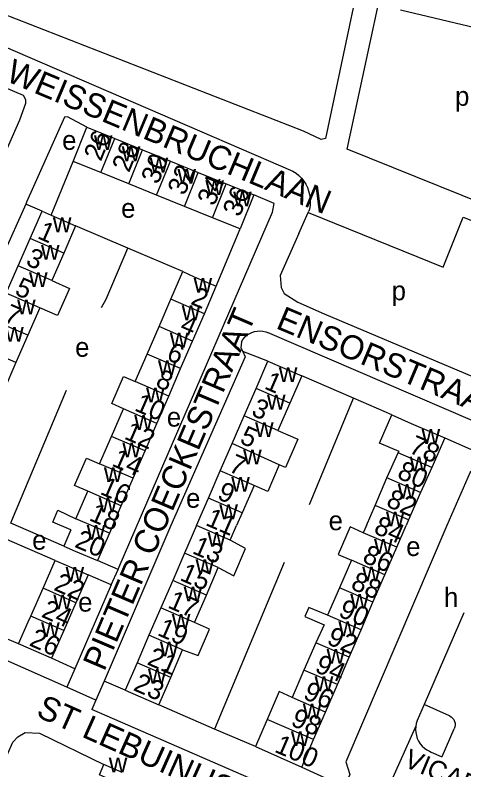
# Model space of a CAD drawing. Extents: x 162804 to 165059, y 381530 to 382901.
# Drawn here: x 163352.5 to 163445.8, y 381949.2 to 382106.1 of the extents above; entities that cross this region are included whole.
import ezdxf

# ---------------------------------------------------------------- set-up
doc = ezdxf.new("R2010")
doc.units = 0
for name, color, linetype in [('BLT_Basislijn', 7, 'Continuous'), ('BLT_Bebouwing', 7, 'Continuous'), ('BLT_Centroide', 7, 'Continuous'), ('BLT_Huisnummer', 7, 'Continuous'), ('BLT_Huisnummer_ tussenligend', 7, 'Continuous'), ('BLT_Onderverdeling_panden', 7, 'Continuous'), ('BLT_Straatnaam', 7, 'Continuous'), ('BLT_Straatnaam_verkleind', 7, 'Continuous'), ('BLT_Vlakafsluiter', 7, 'Continuous')]:
    doc.layers.add(name, color=color, linetype=linetype)

msp = doc.modelspace()

# ---------------------------------------------------------------- linework, layer by layer
at = {"layer": 'BLT_Basislijn'}
for p, q in [((163432.58, 382107.21), (163472.75, 382097.61)), ((163350, 382099.73), (163410.26, 382073.66)), ((163359.99, 382064.53), (163364.56, 382075.71)), ((163354.73, 382066.84), (163350, 382056.14)), ((163358.12, 382065.34), (163354.73, 382066.84)), ((163411.46, 382060.73), (163413.44, 382065.06)), ((163413.44, 382065.06), (163413.57, 382065.34)), ((163375.96, 382057.66), (163365.08, 382062.3)), ((163394.32, 382049.74), (163399.3, 382061.66)), ((163387.36, 382052.79), (163375.96, 382057.66)), ((163447.67, 382021.74), (163404.98, 382040.15)), ((163405.06, 382034.18), (163399.81, 382036.15)), ((163422.85, 382026.47), (163412.07, 382031.14)), ((163413.67, 382004.4), (163422.85, 382026.47)), ((163430.8, 382023.05), (163422.85, 382026.47)), ((163441.79, 382018.23), (163450.32, 382014.5)), ((163362.64, 381995.71), (163351.65, 382000.48)), ((163384.9, 382000), (163371.02, 381967.68)), ((163442.21, 382000), (163421.25, 381950.88)), ((163360.86, 381992.74), (163350.32, 381997.3)), ((163373.9, 381990.88), (163369.63, 381992.72)), ((163408.41, 381992.34), (163393.95, 381957.7)), ((163372.51, 381987.67), (163373.9, 381990.88)), ((163372.51, 381987.67), (163367.69, 381989.74)), ((163372.51, 381987.67), (163364.95, 381970.23)), ((163445.79, 381981.86), (163437.52, 381962.79)), ((163353.24, 381975.42), (163350, 381976.82)), ((163363.28, 381966.38), (163350, 381972.31)), ((163364.95, 381970.23), (163360.07, 381972.42)), ((163364.95, 381970.23), (163363.28, 381966.38)), ((163371.02, 381967.68), (163369.31, 381963.68)), ((163375.38, 381965.8), (163371.02, 381967.68)), ((163369.31, 381963.68), (163363.28, 381966.38)), ((163369.31, 381963.68), (163368.49, 381961.77)), ((163393.95, 381957.7), (163382.39, 381962.76)), ((163437.52, 381962.79), (163436.08, 381959.47)), ((163442.79, 381960.44), (163437.52, 381962.79)), ((163414.35, 381941.82), (163368.49, 381961.77)), ((163402.45, 381954.04), (163393.95, 381957.7)), ((163412.08, 381949.8), (163420.93, 381945.73))]:
    msp.add_line(p, q, dxfattribs=at)
for points in [[(163350, 382150.26), (163427.51, 382132.02), (163427.76, 382131.26), (163417.05, 382080.47), (163416.15, 382080.25), (163412.43, 382081.95), (163350, 382106.4)], [(163461.51, 382062.99), (163459.69, 382062.86), (163421.54, 382078.27), (163432.84, 382130.7), (163443.64, 382128.25), (163444.42, 382128.06), (163445.13, 382121.86)], [(163350, 382076.32), (163353.5, 382084.32), (163354.76, 382087.77), (163354.75, 382088.47), (163354.27, 382089.42), (163350.18, 382091.16)], [(163367.43, 382082.79), (163363.4, 382084.96), (163362.77, 382084.88), (163354.9, 382067.22), (163354.73, 382066.84)], [(163410.26, 382073.66), (163410.9, 382073.24), (163411.49, 382072.75), (163412.02, 382072.21), (163412.5, 382071.61), (163412.91, 382070.97), (163413.25, 382070.28), (163413.52, 382069.57), (163413.71, 382068.83), (163413.82, 382068.08), (163413.86, 382067.31), (163413.81, 382066.55), (163413.69, 382065.8), (163413.57, 382065.34)], [(163373.9, 381990.88), (163374.12, 381991.39), (163406, 382065.12), (163406.38, 382066.93), (163402.16, 382068.73)], [(163413.44, 382065.06), (163441.5, 382053.69), (163445.66, 382064.13), (163459.84, 382058.5)], [(163411.46, 382060.73), (163407.59, 382051.95), (163407.84, 382049.46), (163408.46, 382048.23), (163411.27, 382046.47), (163416.75, 382043.99), (163449.25, 382030.27)], [(163370.45, 382045.31), (163371.47, 382047.06), (163375.96, 382057.66)], [(163399.55, 382038.22), (163399.87, 382038.71), (163400.25, 382039.16), (163400.69, 382039.55), (163401.18, 382039.88), (163401.71, 382040.14), (163402.27, 382040.33), (163402.85, 382040.43), (163403.43, 382040.47), (163404.02, 382040.41), (163404.6, 382040.29), (163404.98, 382040.15)], [(163399.55, 382038.22), (163399.43, 382036.94), (163399.81, 382036.15)], [(163399.81, 382036.15), (163400.31, 382035.08), (163384.9, 382000)], [(163351.65, 382000.48), (163351.87, 382001.03), (163363.22, 382028.16)], [(163450.32, 382014.5), (163449.61, 382012.54), (163447.08, 382011.09), (163442.21, 382000)], [(163436.08, 381959.47), (163435.89, 381958.87), (163435.77, 381958.25)], [(163442.79, 381960.44), (163443.14, 381960.24), (163443.44, 381959.98), (163443.68, 381959.66), (163443.85, 381959.3), (163443.95, 381958.92), (163443.97, 381958.52), (163443.91, 381958.13), (163443.77, 381957.75)], [(163435.77, 381958.25), (163435.73, 381957.61), (163435.78, 381956.98), (163435.9, 381956.36), (163436.1, 381955.76), (163436.37, 381955.19), (163436.71, 381954.66), (163437.12, 381954.17), (163437.59, 381953.74), (163438.1, 381953.38), (163438.66, 381953.08), (163439.01, 381952.93)], [(163439.01, 381952.93), (163441.05, 381952.02), (163441.24, 381952.02), (163443.77, 381957.75)], [(163350, 381950.24), (163352.04, 381954.98), (163353.09, 381956.07), (163354.59, 381956.96), (163357.61, 381956.86), (163370.93, 381950.32)], [(163421.25, 381950.88), (163422.08, 381948.24), (163420.93, 381945.73)]]:
    msp.add_lwpolyline(points, dxfattribs=at)
at = {"layer": 'BLT_Bebouwing'}
for p, q in [((163364.56, 382075.71), (163367.43, 382082.79)), ((163367.43, 382082.79), (163373.22, 382080.44)), ((163373.22, 382080.44), (163379.01, 382078.1)), ((163379.01, 382078.1), (163384.79, 382075.76)), ((163370.35, 382073.37), (163364.56, 382075.71)), ((163384.79, 382075.76), (163390.58, 382073.42)), ((163376.14, 382071.03), (163370.35, 382073.37)), ((163390.58, 382073.42), (163396.37, 382071.07)), ((163381.93, 382068.68), (163376.14, 382071.03)), ((163396.37, 382071.07), (163402.16, 382068.73)), ((163387.72, 382066.34), (163381.93, 382068.68)), ((163402.16, 382068.73), (163399.3, 382061.66)), ((163393.51, 382064), (163387.72, 382066.34)), ((163355.65, 382059.66), (163358.12, 382065.34)), ((163358.12, 382065.34), (163359.99, 382064.53)), ((163399.3, 382061.66), (163393.51, 382064)), ((163365.08, 382062.3), (163362.61, 382056.62)), ((163353.17, 382053.97), (163355.65, 382059.66)), ((163362.61, 382056.62), (163360.13, 382050.93)), ((163350.69, 382048.28), (163353.17, 382053.97)), ((163384.89, 382047.06), (163387.36, 382052.79)), ((163391.86, 382044.04), (163394.32, 382049.74)), ((163382.42, 382041.36), (163384.89, 382047.06)), ((163357.65, 382045.24), (163355.17, 382039.55)), ((163389.39, 382038.34), (163391.86, 382044.04)), ((163379.95, 382035.65), (163382.42, 382041.36)), ((163355.17, 382039.55), (163352.69, 382033.87)), ((163386.92, 382032.64), (163389.39, 382038.34)), ((163377.49, 382029.95), (163379.95, 382035.65)), ((163352.69, 382033.87), (163350.21, 382028.18)), ((163402.58, 382028.49), (163405.06, 382034.18)), ((163405.06, 382034.18), (163412.07, 382031.14)), ((163384.45, 382026.93), (163386.92, 382032.64)), ((163412.07, 382031.14), (163409.59, 382025.44)), ((163400.11, 382022.79), (163402.58, 382028.49)), ((163381.99, 382021.23), (163384.45, 382026.93)), ((163409.59, 382025.44), (163407.12, 382019.75)), ((163372.55, 382018.54), (163375.02, 382024.24)), ((163397.64, 382017.09), (163400.11, 382022.79)), ((163379.52, 382015.52), (163381.99, 382021.23)), ((163370.08, 382012.84), (163372.55, 382018.54)), ((163441.79, 382018.23), (163439.14, 382012.08)), ((163395.16, 382011.39), (163397.64, 382017.09)), ((163377.05, 382009.82), (163379.52, 382015.52)), ((163429.8, 382009.91), (163432.15, 382015.1)), ((163392.69, 382005.69), (163395.16, 382011.39)), ((163439.14, 382012.08), (163436.76, 382006.9)), ((163374.59, 382004.11), (163377.05, 382009.82)), ((163427.33, 382004.2), (163429.8, 382009.91)), ((163402.17, 382008.35), (163399.7, 382002.65)), ((163365.15, 382001.43), (163367.61, 382007.13)), ((163436.76, 382006.9), (163434.29, 382001.19)), ((163390.21, 381999.99), (163392.69, 382005.69)), ((163372.81, 382000), (163374.59, 382004.11)), ((163425.51, 382000), (163427.33, 382004.2)), ((163399.7, 382002.65), (163398.55, 382000)), ((163372.81, 382000), (163372.11, 381998.41)), ((163390.21, 381999.99), (163387.74, 381994.29)), ((163397.22, 381996.95), (163398.55, 382000)), ((163425.51, 382000), (163424.86, 381998.49)), ((163431.82, 381995.48), (163433.77, 382000)), ((163434.29, 382001.19), (163433.77, 382000)), ((163364.12, 381999.12), (163362.64, 381995.71)), ((163372.11, 381998.41), (163369.63, 381992.72)), ((163429.35, 381989.77), (163431.82, 381995.48)), ((163387.74, 381994.29), (163385.27, 381988.6)), ((163358.32, 381986.97), (163360.86, 381992.74)), ((163422.39, 381992.78), (163419.93, 381987.07)), ((163392.28, 381985.55), (163394.75, 381991.25)), ((163367.69, 381989.74), (163365.15, 381983.97)), ((163426.89, 381984.06), (163429.35, 381989.77)), ((163385.27, 381988.6), (163382.8, 381982.9)), ((163355.78, 381981.19), (163358.32, 381986.97)), ((163419.93, 381987.07), (163417.46, 381981.36)), ((163389.81, 381979.85), (163392.28, 381985.55)), ((163365.15, 381983.97), (163362.61, 381978.19)), ((163382.8, 381982.9), (163380.32, 381977.2)), ((163424.42, 381978.35), (163426.89, 381984.06)), ((163362.61, 381978.19), (163360.07, 381972.42)), ((163421.95, 381972.64), (163424.42, 381978.35)), ((163380.32, 381977.2), (163377.85, 381971.5)), ((163360.07, 381972.42), (163353.24, 381975.42)), ((163414.99, 381975.65), (163412.53, 381969.94)), ((163384.86, 381968.45), (163387.33, 381974.15)), ((163419.48, 381966.93), (163421.95, 381972.64)), ((163377.85, 381971.5), (163375.38, 381965.8)), ((163412.53, 381969.94), (163410.06, 381964.23)), ((163382.39, 381962.76), (163384.86, 381968.45)), ((163417.01, 381961.22), (163419.48, 381966.93)), ((163375.38, 381965.8), (163382.39, 381962.76)), ((163414.55, 381955.51), (163417.01, 381961.22)), ((163404.89, 381959.68), (163402.45, 381954.04)), ((163412.08, 381949.8), (163414.55, 381955.51)), ((163402.45, 381954.04), (163412.08, 381949.8)), ((163374.75, 381948.65), (163370.93, 381950.32))]:
    msp.add_line(p, q, dxfattribs=at)
for points in [[(163359.99, 382064.53), (163362.72, 382063.33), (163365.08, 382062.3)], [(163387.36, 382052.79), (163389.73, 382051.73), (163394.32, 382049.74)], [(163360.13, 382050.93), (163363.82, 382049.3), (163361.34, 382043.66), (163357.65, 382045.24)], [(163375.02, 382024.24), (163372.63, 382025.34), (163375.07, 382030.99), (163377.49, 382029.95)], [(163432.15, 382015.1), (163432.3, 382015.43), (163428.25, 382017.15), (163430.8, 382023.05)], [(163430.8, 382023.05), (163434.81, 382021.25), (163441.79, 382018.23)], [(163407.12, 382019.75), (163411.25, 382017.97), (163408.7, 382012.07), (163407.42, 382012.65)], [(163367.61, 382007.13), (163364.86, 382008.32), (163367.33, 382014.03), (163370.08, 382012.84)], [(163407.42, 382012.65), (163405.03, 382007.11), (163402.17, 382008.35)], [(163364.12, 381999.12), (163360.37, 382000.74), (163361.43, 382003.18), (163365.15, 382001.43)], [(163424.86, 381998.49), (163422.12, 381999.71), (163419.62, 381993.98), (163422.39, 381992.78)], [(163394.75, 381991.25), (163397.95, 381989.53), (163400.42, 381995.23), (163397.22, 381996.95)], [(163362.64, 381995.71), (163365.03, 381994.68), (163369.63, 381992.72)], [(163360.86, 381992.74), (163363.11, 381991.75), (163367.69, 381989.74)], [(163417.46, 381981.36), (163413.54, 381982.96), (163412.74, 381981.1), (163416.71, 381979.38), (163414.99, 381975.65)], [(163353.24, 381975.42), (163355.25, 381980), (163355.78, 381981.19)], [(163387.33, 381974.15), (163390.54, 381972.99), (163392.94, 381978.49), (163389.81, 381979.85)], [(163410.06, 381964.23), (163407.38, 381965.48), (163404.89, 381959.68)], [(163373.83, 381946.53), (163370.05, 381948.17), (163370.93, 381950.32)]]:
    msp.add_lwpolyline(points, dxfattribs=at)
at = {"layer": 'BLT_Onderverdeling_panden'}
for p, q in [((163370.35, 382073.37), (163373.22, 382080.44)), ((163376.14, 382071.03), (163379.01, 382078.1)), ((163381.93, 382068.68), (163384.79, 382075.76)), ((163387.72, 382066.34), (163390.58, 382073.42)), ((163393.51, 382064), (163396.37, 382071.07)), ((163362.61, 382056.62), (163355.65, 382059.66)), ((163360.13, 382050.93), (163353.17, 382053.97)), ((163357.65, 382045.24), (163350.69, 382048.28)), ((163391.86, 382044.04), (163384.89, 382047.06)), ((163355.17, 382039.55), (163350, 382041.81)), ((163389.39, 382038.34), (163382.42, 382041.36)), ((163352.69, 382033.87), (163350, 382035.04)), ((163386.92, 382032.64), (163379.95, 382035.65)), ((163384.45, 382026.93), (163377.49, 382029.95)), ((163409.59, 382025.44), (163402.58, 382028.49)), ((163381.99, 382021.23), (163375.02, 382024.24)), ((163407.12, 382019.75), (163400.11, 382022.79)), ((163379.52, 382015.52), (163372.55, 382018.54)), ((163407.42, 382012.65), (163397.64, 382017.09)), ((163439.14, 382012.08), (163432.15, 382015.1)), ((163377.05, 382009.82), (163370.08, 382012.84)), ((163402.17, 382008.35), (163395.16, 382011.39)), ((163436.76, 382006.9), (163429.8, 382009.91)), ((163374.59, 382004.11), (163367.61, 382007.13)), ((163399.7, 382002.65), (163392.69, 382005.69)), ((163434.29, 382001.19), (163427.33, 382004.2)), ((163372.11, 381998.41), (163365.15, 382001.43)), ((163397.22, 381996.95), (163390.21, 381999.99)), ((163431.82, 381995.48), (163424.86, 381998.49)), ((163394.75, 381991.25), (163387.74, 381994.29)), ((163429.35, 381989.77), (163422.39, 381992.78)), ((163392.28, 381985.55), (163385.27, 381988.6)), ((163365.15, 381983.97), (163358.32, 381986.97)), ((163426.89, 381984.06), (163419.93, 381987.07)), ((163389.81, 381979.85), (163382.8, 381982.9)), ((163362.61, 381978.19), (163355.78, 381981.19)), ((163424.42, 381978.35), (163417.46, 381981.36)), ((163387.33, 381974.15), (163380.32, 381977.2)), ((163421.95, 381972.64), (163414.99, 381975.65)), ((163384.86, 381968.45), (163377.85, 381971.5)), ((163419.48, 381966.93), (163412.53, 381969.94)), ((163417.01, 381961.22), (163410.06, 381964.23)), ((163414.55, 381955.51), (163404.89, 381959.68))]:
    msp.add_line(p, q, dxfattribs=at)
at = {"layer": 'BLT_Vlakafsluiter'}
msp.add_line((163430.49, 381946.29), (163435.77, 381958.25), dxfattribs=at)

# ---------------------------------------------------------------- texts
at = {"layer": 'BLT_Centroide'}
for s, p in [('p', (163443.95, 382087.26)), ('e', (163362.29, 382078.11)), ('w', (163368.89, 382078.08)), ('w', (163374.67, 382075.73)), ('w', (163380.47, 382073.39)), ('w', (163386.25, 382071.05)), ('w', (163392.05, 382068.7)), ('w', (163397.83, 382066.36)), ('e', (163374.55, 382063.98)), ('w', (163360.36, 382060.97)), ('w', (163357.89, 382055.28)), ('w', (163355.41, 382049.59)), ('w', (163389.61, 382048.41)), ('p', (163430.77, 382046.83)), ('w', (163352.92, 382043.91)), ('w', (163387.14, 382042.69)), ('w', (163350.45, 382038.22)), ('w', (163384.67, 382037)), ('e', (163364.99, 382035.09)), ('w', (163382.2, 382031.28)), ('w', (163407.32, 382029.81)), ('w', (163379.73, 382025.59)), ('w', (163404.85, 382024.12)), ('e', (163384.05, 382020.57)), ('w', (163377.27, 382019.88)), ('w', (163402.38, 382018.41)), ('w', (163436.98, 382016.97)), ('w', (163374.8, 382014.19)), ('w', (163399.9, 382012.72)), ('w', (163434.51, 382011.25)), ('w', (163370.96, 382009.06)), ('w', (163397.43, 382007.03)), ('w', (163432.04, 382005.56)), ('e', (163388.04, 382003.7)), ('w', (163369.87, 382002.78)), ('w', (163394.95, 382001.31)), ('e', (163417.67, 381999.03)), ('w', (163429.57, 381999.84)), ('w', (163367.38, 381997.06)), ('w', (163392.48, 381995.62)), ('e', (163356.06, 381994.99)), ('w', (163427.11, 381994.12)), ('e', (163433.79, 381993.67)), ('w', (163390.01, 381989.94)), ('w', (163363, 381988.34)), ('w', (163424.64, 381988.41)), ('w', (163387.54, 381984.22)), ('h', (163441.64, 381983.1)), ('w', (163422.17, 381982.72)), ('w', (163360.46, 381982.59)), ('e', (163365.62, 381982.11)), ('w', (163385.07, 381978.53)), ('w', (163357.92, 381976.81)), ('w', (163419.7, 381977)), ('w', (163382.59, 381972.81)), ('w', (163417.23, 381971.28)), ('w', (163380.12, 381967.12)), ('w', (163414.77, 381965.56)), ('w', (163412.3, 381959.88)), ('w', (163409.84, 381954.16)), ('w', (163371.98, 381948.7))]:
    msp.add_text(s, height=4, dxfattribs=at).set_placement(p)
at = {"layer": 'BLT_Huisnummer'}
for s, rotation, p in [('26', 67.9658, (163370.34, 382075.55)), ('30', 67.9671, (163382.23, 382070.76)), ('36', 67.9616, (163399.2, 382063.98)), ('1', 336.4527, (163356.95, 382059.8)), ('5', 336.4497, (163352.22, 382048.11)), ('2', 336.5935, (163388.81, 382046.12)), ('6', 336.5923, (163383.76, 382034.59)), ('1', 336.5415, (163404.1, 382028.55)), ('10', 336.5842, (163377.12, 382024)), ('5', 336.5436, (163398.98, 382017.23)), ('78', 336.6258, (163434.13, 382015.25)), ('14', 336.5852, (163372.41, 382012.5)), ('9', 336.5397, (163394.31, 382005.62)), ('82', 336.6258, (163429.41, 382004.09)), ('20', 336.845, (163364.68, 381995.61)), ('13', 336.5427, (163389.13, 381994.31)), ('86', 336.6268, (163424.47, 381992.51)), ('22', 336.2691, (163360.36, 381986.68)), ('17', 336.5466, (163384.02, 381983.02)), ('90', 336.6247, (163419.49, 381981.21)), ('26', 336.2722, (163355.25, 381975.14)), ('94', 336.6287, (163414.59, 381969.7)), ('23', 336.5337, (163376.88, 381965.84)), ('100', 336.6305, (163406.21, 381953.03))]:
    msp.add_text(s, height=4, rotation=rotation, dxfattribs=at).set_placement(p)
at = {"layer": 'BLT_Huisnummer_ tussenligend'}
for s, rotation, p in [('28', 67.9658, (163376.19, 382073.22)), ('32', 67.9671, (163387.74, 382068.44)), ('34', 67.9671, (163393.91, 382066.25)), ('3', 336.4527, (163354.53, 382054.25)), ('7', 336.4497, (163349.92, 382042.53)), ('4', 336.5935, (163386.51, 382040.4)), ('8', 336.5923, (163381.48, 382029)), ('3', 336.5415, (163401.39, 382023)), ('12', 336.5842, (163374.99, 382018.12)), ('7', 336.5436, (163396.68, 382011.36)), ('80', 336.6258, (163431.69, 382009.95)), ('16', 336.5852, (163369.98, 382006.63)), ('18', 336.5852, (163367.69, 382001.18)), ('11', 336.5397, (163391.88, 382000.16)), ('84', 336.6258, (163426.82, 381998.51)), ('15', 336.5427, (163386.55, 381988.73)), ('88', 336.6268, (163422.05, 381986.92)), ('24', 336.2691, (163357.77, 381981.1)), ('19', 336.5466, (163381.88, 381977.29)), ('92', 336.6247, (163417.07, 381975.48)), ('21', 336.5466, (163379.74, 381971.21)), ('96', 336.6287, (163412.16, 381964.11)), ('98', 336.6287, (163409.59, 381958.53))]:
    msp.add_text(s, height=4, rotation=rotation, dxfattribs=at).set_placement(p)
at = {"layer": 'BLT_Straatnaam'}
for s, height, rotation, p in [('WEISSENBRUCHLAAN', 5, 337.2526, (163350.34, 382092.51)), ('PIETER COECKESTRAAT', 5, 66.8987, (163371.04, 381969.53)), ('ENSORSTRAAT', 5, 337.1747, (163406.49, 382041.09)), ('ST LEBUINUSLAAN', 4.9999, 335.9225, (163356.65, 381960.43))]:
    msp.add_text(s, height=height, rotation=rotation, dxfattribs=at).set_placement(p)
at = {"layer": 'BLT_Straatnaam_verkleind'}
msp.add_text('VICARIS VAN ALPHENSTRAAT', height=4, rotation=337.2503, dxfattribs=at).set_placement((163433.06, 381950))

doc.saveas('drawing.dxf')
